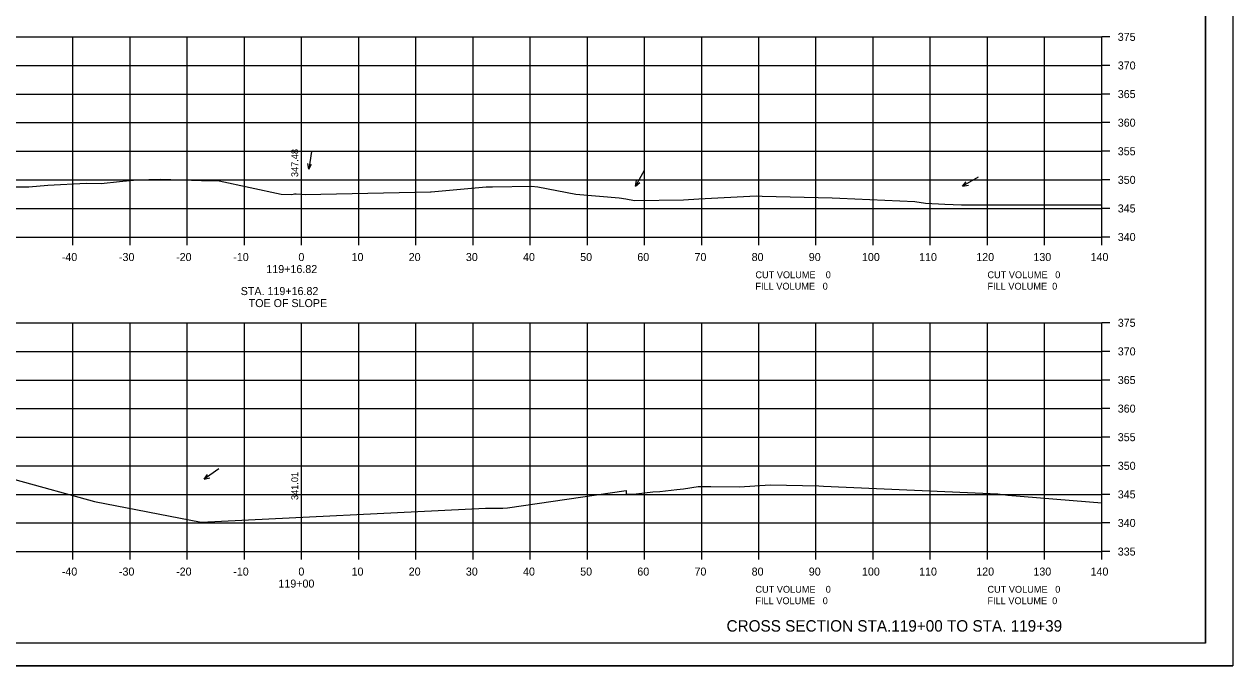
# Model space of a CAD drawing. Extents: x 1374859 to 1376773, y 382242 to 389804.
# Drawn here: x 1376086 to 1376297.5, y 383948.4 to 384060.6 of the extents above; entities that cross this region are included whole.
import ezdxf

# ---------------------------------------------------------------- set-up
doc = ezdxf.new("R2010")
doc.units = 0
for name, color, linetype in [('R_Axis', 7, 'Continuous'), ('R_Axis Annot', 7, 'Continuous'), ('R_Border', 7, 'Continuous'), ('R_Border Notes', 7, 'Continuous'), ('R_Draft', 7, 'Continuous'), ('R_Exist Surface', 7, 'Continuous'), ('R_Grid', 7, 'Continuous'), ('R_No Plot', 7, 'Continuous'), ('R_Water Annot', 7, 'Continuous'), ('R_Xsect Elev', 7, 'Continuous')]:
    doc.layers.add(name, color=color, linetype=linetype)

msp = doc.modelspace()

# ---------------------------------------------------------------- linework, layer by layer
at = {"layer": 'R_Axis'}
for p, q in [((1376274.57, 384023.42), (1376274.57, 384058.42)), ((1376275.97, 384058.42), (1376274.57, 384058.42)), ((1376275.97, 384053.42), (1376274.57, 384053.42)), ((1376275.97, 384048.42), (1376274.57, 384048.42)), ((1376275.97, 384043.42), (1376274.57, 384043.42)), ((1376275.97, 384038.42), (1376274.57, 384038.42)), ((1376275.97, 384033.42), (1376274.57, 384033.42)), ((1376275.97, 384028.42), (1376274.57, 384028.42)), ((1375994.57, 384023.42), (1376274.57, 384023.42)), ((1376094.57, 384022.02), (1376094.57, 384023.42)), ((1376104.57, 384022.02), (1376104.57, 384023.42)), ((1376114.57, 384022.02), (1376114.57, 384023.42)), ((1376124.57, 384022.02), (1376124.57, 384023.42)), ((1376134.57, 384022.02), (1376134.57, 384023.42)), ((1376144.57, 384022.02), (1376144.57, 384023.42)), ((1376154.57, 384022.02), (1376154.57, 384023.42)), ((1376164.57, 384022.02), (1376164.57, 384023.42)), ((1376174.57, 384022.02), (1376174.57, 384023.42)), ((1376184.57, 384022.02), (1376184.57, 384023.42)), ((1376194.57, 384022.02), (1376194.57, 384023.42)), ((1376204.57, 384022.02), (1376204.57, 384023.42)), ((1376214.57, 384022.02), (1376214.57, 384023.42)), ((1376224.57, 384022.02), (1376224.57, 384023.42)), ((1376234.57, 384022.02), (1376234.57, 384023.42)), ((1376244.57, 384022.02), (1376244.57, 384023.42)), ((1376254.57, 384022.02), (1376254.57, 384023.42)), ((1376264.57, 384022.02), (1376264.57, 384023.42)), ((1376274.57, 384022.02), (1376274.57, 384023.42)), ((1376275.97, 384023.42), (1376274.57, 384023.42)), ((1376274.57, 383968.42), (1376274.57, 384008.42)), ((1376275.97, 384008.42), (1376274.57, 384008.42)), ((1376275.97, 384003.42), (1376274.57, 384003.42)), ((1376275.97, 383998.42), (1376274.57, 383998.42)), ((1376275.97, 383993.42), (1376274.57, 383993.42)), ((1376275.97, 383988.42), (1376274.57, 383988.42)), ((1376275.97, 383983.42), (1376274.57, 383983.42)), ((1376275.97, 383978.42), (1376274.57, 383978.42)), ((1376275.97, 383973.42), (1376274.57, 383973.42)), ((1375994.57, 383968.42), (1376274.57, 383968.42)), ((1376094.57, 383967.02), (1376094.57, 383968.42)), ((1376104.57, 383967.02), (1376104.57, 383968.42)), ((1376114.57, 383967.02), (1376114.57, 383968.42)), ((1376124.57, 383967.02), (1376124.57, 383968.42)), ((1376134.57, 383967.02), (1376134.57, 383968.42)), ((1376144.57, 383967.02), (1376144.57, 383968.42)), ((1376154.57, 383967.02), (1376154.57, 383968.42)), ((1376164.57, 383967.02), (1376164.57, 383968.42)), ((1376174.57, 383967.02), (1376174.57, 383968.42)), ((1376184.57, 383967.02), (1376184.57, 383968.42)), ((1376194.57, 383967.02), (1376194.57, 383968.42)), ((1376204.57, 383967.02), (1376204.57, 383968.42)), ((1376214.57, 383967.02), (1376214.57, 383968.42)), ((1376224.57, 383967.02), (1376224.57, 383968.42)), ((1376234.57, 383967.02), (1376234.57, 383968.42)), ((1376244.57, 383967.02), (1376244.57, 383968.42)), ((1376254.57, 383967.02), (1376254.57, 383968.42)), ((1376264.57, 383967.02), (1376264.57, 383968.42)), ((1376274.57, 383967.02), (1376274.57, 383968.42)), ((1376275.97, 383968.42), (1376274.57, 383968.42))]:
    msp.add_line(p, q, dxfattribs=at)
at = {"layer": 'R_Border'}
for q in [(1376292.75, 384157.88), (1375976.57, 383952.42)]:
    msp.add_line((1376292.75, 383952.42), q, dxfattribs=at)
at = {"layer": 'R_Exist Surface'}
for points in [[(1376079.18, 384032.18), (1376086.86, 384032.22), (1376090.15, 384032.47), (1376096.9, 384032.83), (1376099.49, 384032.76), (1376102.7, 384033.14), (1376105.73, 384033.45), (1376109.92, 384033.52), (1376117.08, 384033.32), (1376120.14, 384033.23), (1376130.99, 384030.94), (1376132.85, 384030.85), (1376133.34, 384030.95), (1376133.6, 384030.97), (1376135.18, 384030.87), (1376157.14, 384031.34), (1376157.26, 384031.33), (1376166.89, 384032.18), (1376167, 384032.18), (1376167.97, 384032.2), (1376174.77, 384032.31), (1376175.88, 384032.22), (1376182.54, 384030.94), (1376190.16, 384030.3), (1376191.29, 384030.1), (1376192.83, 384029.81), (1376201.39, 384029.9), (1376204.08, 384030.12), (1376214.09, 384030.62), (1376215.15, 384030.58), (1376227.4, 384030.28), (1376228.77, 384030.22), (1376241.86, 384029.61), (1376243.72, 384029.32), (1376247.11, 384029.16), (1376250.02, 384029.05), (1376274.57, 384029.07)], [(1376084.4, 383981.03), (1376098.32, 383977.16), (1376116.99, 383973.56), (1376166.74, 383976.02), (1376169.78, 383976.02), (1376170.58, 383976.09), (1376191.33, 383979.08), (1376191.36, 383978.46), (1376193.13, 383978.5), (1376196, 383978.87), (1376197.26, 383978.94), (1376200.2, 383979.3), (1376201.39, 383979.4), (1376203.93, 383979.78), (1376206.17, 383979.82), (1376211.17, 383979.76), (1376216.57, 383980.08), (1376225.07, 383979.89), (1376225.9, 383979.84), (1376256.37, 383978.52), (1376258.11, 383978.31), (1376274.57, 383976.96)]]:
    msp.add_lwpolyline(points, dxfattribs=at)
at = {"layer": 'R_Grid'}
for p, q in [((1375994.57, 384058.42), (1376274.57, 384058.42)), ((1376094.57, 384023.42), (1376094.57, 384058.42)), ((1376104.57, 384023.42), (1376104.57, 384058.42)), ((1376114.57, 384023.42), (1376114.57, 384058.42)), ((1376124.57, 384023.42), (1376124.57, 384058.42)), ((1376134.57, 384023.42), (1376134.57, 384058.42)), ((1376144.57, 384023.42), (1376144.57, 384058.42)), ((1376154.57, 384023.42), (1376154.57, 384058.42)), ((1376164.57, 384023.42), (1376164.57, 384058.42)), ((1376174.57, 384023.42), (1376174.57, 384058.42)), ((1376184.57, 384023.42), (1376184.57, 384058.42)), ((1376194.57, 384023.42), (1376194.57, 384058.42)), ((1376204.57, 384023.42), (1376204.57, 384058.42)), ((1376214.57, 384023.42), (1376214.57, 384058.42)), ((1376224.57, 384023.42), (1376224.57, 384058.42)), ((1376234.57, 384023.42), (1376234.57, 384058.42)), ((1376244.57, 384023.42), (1376244.57, 384058.42)), ((1376254.57, 384023.42), (1376254.57, 384058.42)), ((1376264.57, 384023.42), (1376264.57, 384058.42)), ((1376274.57, 384023.42), (1376274.57, 384058.42)), ((1375994.57, 384053.42), (1376274.57, 384053.42)), ((1375994.57, 384048.42), (1376274.57, 384048.42)), ((1375994.57, 384043.42), (1376274.57, 384043.42)), ((1375994.57, 384038.42), (1376274.57, 384038.42)), ((1375994.57, 384033.42), (1376274.57, 384033.42)), ((1375994.57, 384028.42), (1376274.57, 384028.42)), ((1375994.57, 384023.42), (1376274.57, 384023.42)), ((1375994.57, 384008.42), (1376274.57, 384008.42)), ((1376094.57, 383968.42), (1376094.57, 384008.42)), ((1376104.57, 383968.42), (1376104.57, 384008.42)), ((1376114.57, 383968.42), (1376114.57, 384008.42)), ((1376124.57, 383968.42), (1376124.57, 384008.42)), ((1376134.57, 383968.42), (1376134.57, 384008.42)), ((1376144.57, 383968.42), (1376144.57, 384008.42)), ((1376154.57, 383968.42), (1376154.57, 384008.42)), ((1376164.57, 383968.42), (1376164.57, 384008.42)), ((1376174.57, 383968.42), (1376174.57, 384008.42)), ((1376184.57, 383968.42), (1376184.57, 384008.42)), ((1376194.57, 383968.42), (1376194.57, 384008.42)), ((1376204.57, 383968.42), (1376204.57, 384008.42)), ((1376214.57, 383968.42), (1376214.57, 384008.42)), ((1376224.57, 383968.42), (1376224.57, 384008.42)), ((1376234.57, 383968.42), (1376234.57, 384008.42)), ((1376244.57, 383968.42), (1376244.57, 384008.42)), ((1376254.57, 383968.42), (1376254.57, 384008.42)), ((1376264.57, 383968.42), (1376264.57, 384008.42)), ((1376274.57, 383968.42), (1376274.57, 384008.42)), ((1375994.57, 384003.42), (1376274.57, 384003.42)), ((1375994.57, 383998.42), (1376274.57, 383998.42)), ((1375994.57, 383993.42), (1376274.57, 383993.42)), ((1375994.57, 383988.42), (1376274.57, 383988.42)), ((1375994.57, 383983.42), (1376274.57, 383983.42)), ((1375994.57, 383978.42), (1376274.57, 383978.42)), ((1375994.57, 383973.42), (1376274.57, 383973.42)), ((1375994.57, 383968.42), (1376274.57, 383968.42))]:
    msp.add_line(p, q, dxfattribs=at)
at = {"layer": 'R_No Plot'}
msp.add_line((1375964.17, 383948.45), (1376297.5, 383948.45), dxfattribs=at)
for points in [[(1375964.16, 384161.78), (1376297.5, 384161.78), (1376297.5, 383948.44), (1375964.16, 383948.44)], [(1376210.49, 384157.88), (1376210.49, 384148), (1376246.22, 384148), (1376246.22, 384145.08), (1376269.42, 384145.08), (1376269.42, 384120.75), (1376292.75, 384120.75), (1376292.75, 383952.42), (1375976.57, 383952.42), (1375976.57, 384157.88)]]:
    msp.add_lwpolyline(points, close=True, dxfattribs=at)
at = {"layer": 'R_Water Annot'}
for p, q in [((1376136.32, 384038.39), (1376135.84, 384035.29)), ((1376135.84, 384035.29), (1376135.64, 384036.29)), ((1376135.84, 384035.29), (1376136.33, 384036.18)), ((1376194.51, 384035.05), (1376192.99, 384032.29)), ((1376252.93, 384033.9), (1376250.23, 384032.29)), ((1376192.99, 384032.29), (1376193.15, 384033.31)), ((1376192.99, 384032.29), (1376193.76, 384032.97)), ((1376250.23, 384032.29), (1376250.87, 384033.09)), ((1376250.23, 384032.29), (1376251.23, 384032.49)), ((1376120.08, 383982.89), (1376117.52, 383981.06)), ((1376117.52, 383981.06), (1376118.1, 383981.91)), ((1376117.52, 383981.06), (1376118.51, 383981.34))]:
    msp.add_line(p, q, dxfattribs=at)

# ---------------------------------------------------------------- texts
at = {"layer": 'R_Axis Annot'}
for s, height, p in [('375', 1.4, (1376277.37, 384057.72)), ('370', 1.4, (1376277.37, 384052.72)), ('365', 1.4, (1376277.37, 384047.72)), ('360', 1.4, (1376277.37, 384042.72)), ('355', 1.4, (1376277.37, 384037.72)), ('350', 1.4, (1376277.37, 384032.72)), ('345', 1.4, (1376277.37, 384027.72)), ('340', 1.4, (1376277.37, 384022.72)), ('-40', 1.4, (1376092.61, 384019.22)), ('-30', 1.4, (1376102.61, 384019.22)), ('-20', 1.4, (1376112.61, 384019.22)), ('-10', 1.4, (1376122.61, 384019.22)), ('0', 1.4, (1376134.01, 384019.22)), ('10', 1.4, (1376143.31, 384019.22)), ('20', 1.4, (1376153.31, 384019.22)), ('30', 1.4, (1376163.31, 384019.22)), ('40', 1.4, (1376173.31, 384019.22)), ('50', 1.4, (1376183.31, 384019.22)), ('60', 1.4, (1376193.31, 384019.22)), ('70', 1.4, (1376203.31, 384019.22)), ('80', 1.4, (1376213.31, 384019.22)), ('90', 1.4, (1376223.31, 384019.22)), ('100', 1.4, (1376232.61, 384019.22)), ('110', 1.4, (1376242.61, 384019.22)), ('120', 1.4, (1376252.61, 384019.22)), ('130', 1.4, (1376262.61, 384019.22)), ('140', 1.4, (1376272.61, 384019.22)), ('119+16.82', 1.4, (1376128.4, 384017.12)), ('CUT VOLUME    0', 1.2, (1376213.97, 384016.22)), ('CUT VOLUME   0', 1.2, (1376254.57, 384016.22)), ('FILL VOLUME   0', 1.2, (1376213.97, 384014.22)), ('FILL VOLUME  0', 1.2, (1376254.57, 384014.22)), ('375', 1.4, (1376277.37, 384007.72)), ('370', 1.4, (1376277.37, 384002.72)), ('365', 1.4, (1376277.37, 383997.72)), ('360', 1.4, (1376277.37, 383992.72)), ('355', 1.4, (1376277.37, 383987.72)), ('350', 1.4, (1376277.37, 383982.72)), ('345', 1.4, (1376277.37, 383977.72)), ('340', 1.4, (1376277.37, 383972.72)), ('335', 1.4, (1376277.37, 383967.72)), ('-40', 1.4, (1376092.61, 383964.22)), ('-30', 1.4, (1376102.61, 383964.22)), ('-20', 1.4, (1376112.61, 383964.22)), ('-10', 1.4, (1376122.61, 383964.22)), ('0', 1.4, (1376134.01, 383964.22)), ('10', 1.4, (1376143.31, 383964.22)), ('20', 1.4, (1376153.31, 383964.22)), ('30', 1.4, (1376163.31, 383964.22)), ('40', 1.4, (1376173.31, 383964.22)), ('50', 1.4, (1376183.31, 383964.22)), ('60', 1.4, (1376193.31, 383964.22)), ('70', 1.4, (1376203.31, 383964.22)), ('80', 1.4, (1376213.31, 383964.22)), ('90', 1.4, (1376223.31, 383964.22)), ('100', 1.4, (1376232.61, 383964.22)), ('110', 1.4, (1376242.61, 383964.22)), ('120', 1.4, (1376252.61, 383964.22)), ('130', 1.4, (1376262.61, 383964.22)), ('140', 1.4, (1376272.61, 383964.22)), ('119+00', 1.4, (1376130.51, 383962.12)), ('CUT VOLUME    0', 1.2, (1376213.97, 383961.22)), ('CUT VOLUME   0', 1.2, (1376254.57, 383961.22)), ('FILL VOLUME   0', 1.2, (1376213.97, 383959.22)), ('FILL VOLUME  0', 1.2, (1376254.57, 383959.22))]:
    msp.add_text(s, height=height, dxfattribs=at).set_placement(p)
at = {"layer": 'R_Border Notes'}
for s, p in [('STA. 119+16.82', (1376123.92, 384013.27)), ('TOE OF SLOPE', (1376125.31, 384011.17))]:
    msp.add_text(s, height=1.4, dxfattribs=at).set_placement(p)
at = {"layer": 'R_Draft'}
msp.add_text('CROSS SECTION STA.119+00 TO STA. 119+39', height=2, dxfattribs=at).set_placement((1376208.92, 383954.42))
at = {"layer": 'R_Xsect Elev'}
for s, p in [('347.48', (1376133.97, 384033.91)), ('341.01', (1376133.97, 383977.43))]:
    msp.add_text(s, height=1.2, rotation=90, dxfattribs=at).set_placement(p)

doc.saveas('drawing.dxf')
